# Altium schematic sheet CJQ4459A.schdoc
size 127 x 101 mm
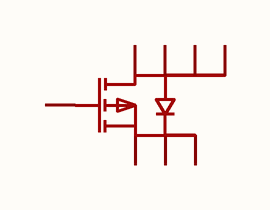
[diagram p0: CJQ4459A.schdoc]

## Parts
Q?  cjq4459a  [SOP-8_L4.9-W3.9-P1.27-LS6.0-BL]  (value not drawn)

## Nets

Not connected (* = marked no-connect by the designer): Q? 1(S) 2(S) 3(S) 4(G) 5(D) 6(D) 7(D) 8(D)

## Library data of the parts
Q? = cjq4459a: 数量:1个P沟道;漏源电压(Vdss):30V;连续漏极电流(Id):6A;导通电阻(RDS(on)):40mΩ@4.5V;耗散功率(Pd):2.3W;阈值电压(Vgs(th)):1.6V;; Manufacturer: CJ(江苏长电/长晶); AddInBom: yes; ModelId: 75c24a7891ee4dd6bdac16a7163ff87e; ModelName: SOP-8_L4.9-W3.9-P1.27-LS6.0-BL-1; ModelTransform: 192.913,236.22,0,0,0,0,-0.393,2.749,0; Number: 1个P沟道; Drain to Source Voltage: 30V; Current - Continuous Drain(Id): 6A; Pd - Power Dissipation: 2.3W; Gate Threshold Voltage (Vgs(th)): 1.6V; Gate Charge(Qg): 13.4nC@10V; Input Capacitance(Ciss): 760pF; Reverse Transfer Capacitance (Crss@Vds): 66pF; Type: P沟道; Output Capacitance(Coss): 107pF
